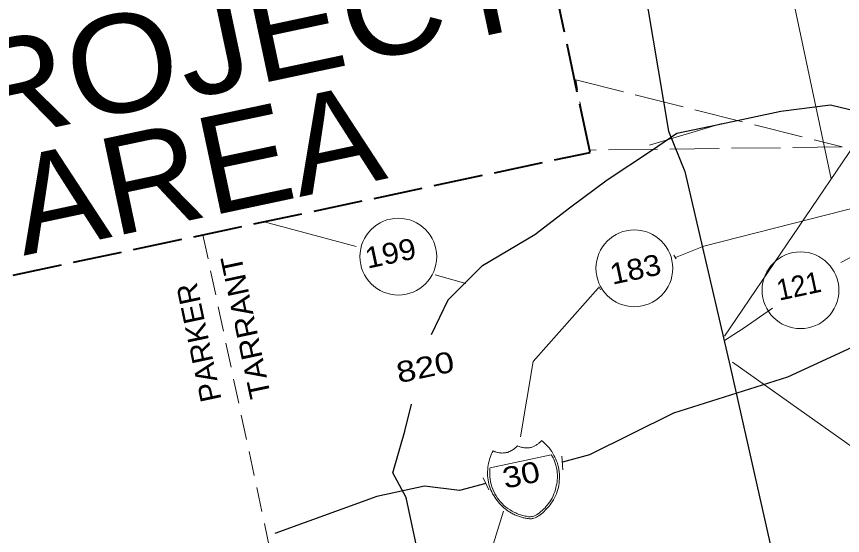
# Model space of a CAD drawing. Extents: x 2357218 to 2371708, y 6973728 to 6980157.
# Drawn here: x 2357321.4 to 2357522.9, y 6974620.2 to 6974746.8 of the extents above; entities that cross this region are included whole.
import ezdxf

# ---------------------------------------------------------------- set-up
doc = ezdxf.new("R2010")
doc.units = 0
doc.header["$LTSCALE"] = 2
doc.linetypes.add('LONG_DASHED', pattern=[7.5, 6, -1.5])
doc.linetypes.add('MEDIUM_DASHED', pattern=[4.5, 3, -1.5])
doc.layers.add('62', color=7, linetype='Continuous', lineweight=13)
doc.layers.add('63', color=7, linetype='Continuous', lineweight=13)

msp = doc.modelspace()

# ---------------------------------------------------------------- linework, layer by layer
at = {"layer": '62'}
for p, q in [((2357520.159, 6974707.242), (2357511.041, 6974750.139)), ((2357529.782, 6974721.388), (2357494.082, 6974668.875)), ((2357475.798, 6974715.388), (2357493.426, 6974720.675)), ((2357381.785, 6974696.74), (2357404.235, 6974690.7)), ((2357522.449, 6974686.841), (2357528.402, 6974689.897)), ((2357481.765, 6974688.614), (2357482.328, 6974687.698)), ((2357423.49, 6974683.774), (2357430.97, 6974681.704)), ((2357463.555, 6974680.671), (2357463.3, 6974680.571)), ((2357463.457, 6974680.927), (2357463.854, 6974680.137)), ((2357498.622, 6974670.689), (2357505.78, 6974675.636)), ((2357498.622, 6974670.689), (2357494.066, 6974667.766)), ((2357454.458, 6974639.583), (2357454.681, 6974636.273)), ((2357435.253, 6974634.282), (2357436.574, 6974631.412)), ((2357440.151, 6974626.169), (2357432.971, 6974602.904))]:
    msp.add_line(p, q, dxfattribs=at)
at = {"layer": '62', "linetype": 'MEDIUM_DASHED'}
msp.add_line((2357366.864, 6974693.567), (2357405.498, 6974511.924), dxfattribs=at)
at = {"layer": '62', "lineweight": 25}
for p, q in [((2357426.636, 6974677.632), (2357422.517, 6974669.187)), ((2357416.135, 6974645.654), (2357417.77, 6974652.238))]:
    msp.add_line(p, q, dxfattribs=at)
at = {"layer": '62', "linetype": 'LONG_DASHED', "lineweight": 40}
msp.add_lwpolyline([(2357277.991, 6974739.919), (2357291.257, 6974677.497), (2357461.31, 6974713.643), (2357448.042, 6974776.064), (2357277.682, 6974739.853)], dxfattribs=at)
at = {"layer": '62', "lineweight": 25}
for points in [[(2357472.928, 6974763.32), (2357480.438, 6974718.79), (2357484.401, 6974709.004)], [(2357426.636, 6974677.632), (2357435.051, 6974686.092), (2357447.82, 6974693.662), (2357456.605, 6974700.382), (2357465.446, 6974706.953), (2357476.319, 6974714.14), (2357482.491, 6974718.329), (2357492.265, 6974720.406), (2357507.868, 6974723.722), (2357519.974, 6974725.216), (2357526.369, 6974723.698), (2357529.782, 6974721.388)], [(2357484.401, 6974709.004), (2357495.501, 6974661.441), (2357507.761, 6974607.022), (2357528.73, 6974538.67), (2357551.355, 6974511.341)], [(2357525.137, 6974666.085), (2357509.492, 6974658.827), (2357481.662, 6974650.034), (2357461.178, 6974639.907), (2357454.572, 6974638.088)], [(2357596.715, 6974637.66), (2357589.374, 6974634.536), (2357579.785, 6974631.6), (2357566.27, 6974627.645), (2357556.498, 6974625.57), (2357549.681, 6974623.223), (2357545.38, 6974619.435), (2357535.992, 6974615.437), (2357522.037, 6974613.553), (2357509.283, 6974611.762), (2357495.348, 6974609.674), (2357474.275, 6974602.318), (2357453.198, 6974600.715), (2357435.858, 6974601.009), (2357424.93, 6974604.275), (2357419.167, 6974616.556), (2357416.416, 6974629.495), (2357413.211, 6974635.486), (2357416.135, 6974645.654)], [(2357435.859, 6974632.939), (2357429.444, 6974631.183), (2357420.936, 6974632.25), (2357409.294, 6974629.777), (2357384.44, 6974620.72)]]:
    msp.add_lwpolyline(points, dxfattribs=at)
at = {"layer": '62', "linetype": 'LONG_DASHED'}
for points in [[(2357457.8, 6974731.348), (2357522.794, 6974714.981), (2357461.163, 6974714.231)], [(2357457.8, 6974731.348), (2357522.794, 6974714.981), (2357461.163, 6974714.231), (2357457.8, 6974731.348)]]:
    msp.add_lwpolyline(points, close=True, dxfattribs=at)
at = {"layer": '62'}
for points in [[(2357556.226, 6974710.287), (2357535.978, 6974702.736), (2357489.081, 6974690.789), (2357482.118, 6974688.043)], [(2357463.3, 6974680.571), (2357447.465, 6974662.645), (2357444.296, 6974644.325)], [(2357544.214, 6974627.95), (2357523.929, 6974642.757), (2357496.053, 6974662.527)], [(2357444.395, 6974641.814), (2357444.611, 6974641.768), (2357444.805, 6974641.719), (2357444.996, 6974641.689), (2357445.212, 6974641.643), (2357445.421, 6974641.641), (2357445.589, 6974641.609), (2357445.794, 6974641.607), (2357445.975, 6974641.621), (2357446.182, 6974641.619), (2357446.369, 6974641.614), (2357446.567, 6974641.655), (2357446.765, 6974641.697), (2357446.941, 6974641.734), (2357447.115, 6974641.772), (2357447.305, 6974641.86), (2357447.472, 6974641.939), (2357447.643, 6974642), (2357447.833, 6974642.086), (2357447.995, 6974642.19), (2357448.162, 6974642.271), (2357448.341, 6974642.4), (2357448.524, 6974642.509), (2357448.682, 6974642.635), (2357448.841, 6974642.761), (2357448.996, 6974642.888), (2357449.149, 6974643.033), (2357449.342, 6974643.213), (2357449.49, 6974643.381), (2357449.796, 6974643.125), (2357450.133, 6974642.849), (2357450.448, 6974642.55), (2357450.749, 6974642.222), (2357451.052, 6974641.873), (2357451.385, 6974641.507), (2357451.675, 6974641.108), (2357451.968, 6974640.711), (2357452.23, 6974640.236), (2357452.485, 6974639.785), (2357452.743, 6974639.335), (2357452.962, 6974638.852), (2357453.156, 6974638.364), (2357453.33, 6974637.872), (2357453.475, 6974637.397), (2357453.609, 6974636.873), (2357453.7, 6974636.339), (2357453.779, 6974635.758), (2357453.829, 6974635.194), (2357453.87, 6974634.675), (2357453.875, 6974634.124), (2357453.809, 6974633.557), (2357453.758, 6974633.039), (2357453.713, 6974632.501), (2357453.597, 6974631.97), (2357453.433, 6974631.43), (2357453.282, 6974630.937), (2357453.099, 6974630.414), (2357452.881, 6974629.91), (2357452.641, 6974629.421), (2357452.378, 6974628.929), (2357452.066, 6974628.446), (2357451.819, 6974628.095), (2357451.576, 6974627.722), (2357451.306, 6974627.365), (2357451.031, 6974627.03), (2357450.709, 6974626.709), (2357450.387, 6974626.389), (2357450.081, 6974626.094), (2357449.776, 6974625.799), (2357449.461, 6974625.549), (2357449.146, 6974625.298), (2357448.827, 6974625.069), (2357448.482, 6974624.856), (2357448.208, 6974624.729), (2357447.898, 6974624.572), (2357447.622, 6974624.467), (2357447.362, 6974624.39)], [(2357447.362, 6974624.39), (2357447.182, 6974624.372), (2357447.029, 6974624.341), (2357446.825, 6974624.32), (2357446.661, 6974624.333), (2357446.497, 6974624.343), (2357446.292, 6974624.346), (2357446.079, 6974624.368), (2357445.865, 6974624.393), (2357445.649, 6974624.439), (2357445.439, 6974624.462), (2357445.193, 6974624.526), (2357444.998, 6974624.576), (2357444.762, 6974624.617), (2357444.539, 6974624.686), (2357444.311, 6974624.776), (2357444.071, 6974624.839), (2357443.842, 6974624.928), (2357443.594, 6974625.014), (2357443.342, 6974625.122), (2357443.138, 6974625.217), (2357442.912, 6974625.307), (2357442.673, 6974625.44), (2357442.422, 6974625.546), (2357442.236, 6974625.669), (2357442.006, 6974625.781), (2357441.797, 6974625.898), (2357441.563, 6974626.03), (2357441.375, 6974626.153), (2357441.161, 6974626.292), (2357440.974, 6974626.413), (2357440.804, 6974626.56), (2357440.614, 6974626.704), (2357440.247, 6974627.016), (2357439.898, 6974627.356), (2357439.55, 6974627.698), (2357439.243, 6974628.045), (2357438.913, 6974628.413), (2357438.605, 6974628.783), (2357438.317, 6974629.16), (2357438.044, 6974629.586), (2357437.803, 6974629.971), (2357437.543, 6974630.424), (2357437.338, 6974630.861), (2357437.128, 6974631.299), (2357436.937, 6974631.767), (2357436.789, 6974632.24), (2357436.634, 6974632.759), (2357436.508, 6974633.236), (2357436.44, 6974633.776), (2357436.38, 6974634.269), (2357436.318, 6974634.784), (2357436.318, 6974635.314), (2357436.323, 6974635.845), (2357436.352, 6974636.356), (2357436.403, 6974636.874), (2357436.448, 6974637.411), (2357436.554, 6974637.895), (2357436.658, 6974638.377), (2357436.789, 6974638.841), (2357436.947, 6974639.288), (2357437.112, 6974639.716), (2357437.258, 6974640.115), (2357437.45, 6974640.501), (2357437.627, 6974640.859), (2357437.853, 6974640.769), (2357438.079, 6974640.679), (2357438.301, 6974640.612), (2357438.473, 6974640.555), (2357438.689, 6974640.509), (2357438.886, 6974640.461), (2357439.099, 6974640.437), (2357439.313, 6974640.392), (2357439.499, 6974640.384), (2357439.69, 6974640.353), (2357439.896, 6974640.353), (2357440.077, 6974640.368), (2357440.286, 6974640.368), (2357440.471, 6974640.36), (2357440.647, 6974640.397), (2357440.868, 6974640.444), (2357441.023, 6974640.477), (2357441.217, 6974640.518), (2357441.387, 6974640.602), (2357441.573, 6974640.686), (2357441.745, 6974640.745), (2357441.912, 6974640.826), (2357442.097, 6974640.937), (2357442.285, 6974641.022), (2357442.421, 6974641.143), (2357442.605, 6974641.249), (2357442.783, 6974641.381), (2357442.962, 6974641.511), (2357443.101, 6974641.63), (2357443.272, 6974641.786), (2357443.42, 6974641.954), (2357443.592, 6974642.127), (2357443.796, 6974642.034), (2357443.979, 6974641.934), (2357444.2, 6974641.866), (2357444.395, 6974641.814)]]:
    msp.add_lwpolyline(points, dxfattribs=at)
msp.add_lwpolyline([(2357451.806, 6974639.941), (2357436.907, 6974636.774), (2357436.888, 6974636.537), (2357436.838, 6974636.231), (2357436.816, 6974635.903), (2357436.836, 6974635.494), (2357436.818, 6974635.03), (2357436.837, 6974634.505), (2357436.905, 6974633.965), (2357437.012, 6974633.346), (2357437.162, 6974632.755), (2357437.342, 6974632.128), (2357437.557, 6974631.551), (2357437.793, 6974630.981), (2357438.073, 6974630.42), (2357438.362, 6974629.93), (2357438.707, 6974629.381), (2357439.063, 6974628.903), (2357439.434, 6974628.454), (2357439.851, 6974628.013), (2357440.289, 6974627.579), (2357440.766, 6974627.172), (2357441.278, 6974626.821), (2357441.792, 6974626.471), (2357442.336, 6974626.174), (2357442.905, 6974625.879), (2357443.166, 6974625.729), (2357443.463, 6974625.63), (2357443.748, 6974625.482), (2357444.066, 6974625.389), (2357444.32, 6974625.284), (2357444.617, 6974625.184), (2357444.909, 6974625.109), (2357445.222, 6974625.039), (2357445.489, 6974624.979), (2357445.776, 6974624.926), (2357446.064, 6974624.872), (2357446.303, 6974624.831), (2357446.56, 6974624.816), (2357446.786, 6974624.819), (2357447.034, 6974624.849), (2357447.26, 6974624.873), (2357447.555, 6974624.983), (2357447.922, 6974625.105), (2357448.224, 6974625.309), (2357448.615, 6974625.528), (2357448.956, 6974625.763), (2357449.284, 6974626.063), (2357449.637, 6974626.346), (2357449.981, 6974626.671), (2357450.324, 6974627.02), (2357450.612, 6974627.379), (2357450.91, 6974627.718), (2357451.201, 6974628.081), (2357451.475, 6974628.415), (2357451.684, 6974628.733), (2357451.887, 6974629.076), (2357452.033, 6974629.361), (2357452.265, 6974629.892), (2357452.479, 6974630.399), (2357452.673, 6974630.9), (2357452.837, 6974631.418), (2357452.969, 6974631.883), (2357453.075, 6974632.365), (2357453.181, 6974632.826), (2357453.243, 6974633.297), (2357453.304, 6974633.77), (2357453.35, 6974634.196), (2357453.345, 6974634.655), (2357453.324, 6974635.087), (2357453.278, 6974635.515), (2357453.256, 6974635.948), (2357453.165, 6974636.365), (2357453.105, 6974636.764), (2357452.952, 6974637.376), (2357452.795, 6974637.894), (2357452.621, 6974638.389), (2357452.461, 6974638.813), (2357452.267, 6974639.187), (2357452.092, 6974639.471), (2357451.945, 6974639.74)], close=True, dxfattribs=at)
for centre in [(2357414.526, 6974688.233), (2357472.114, 6974685.387), (2357512.647, 6974680.037)]:
    msp.add_circle(centre, 9.364, dxfattribs=at)
at = {"layer": '63'}
for p, q in [((2357520.159, 6974707.242), (2357511.041, 6974750.139)), ((2357529.782, 6974721.388), (2357494.082, 6974668.875)), ((2357475.798, 6974715.388), (2357493.426, 6974720.675)), ((2357381.785, 6974696.74), (2357404.235, 6974690.7)), ((2357522.449, 6974686.841), (2357528.402, 6974689.897)), ((2357481.765, 6974688.614), (2357482.328, 6974687.698)), ((2357423.49, 6974683.774), (2357430.97, 6974681.704)), ((2357463.555, 6974680.671), (2357463.3, 6974680.571)), ((2357463.457, 6974680.927), (2357463.854, 6974680.137)), ((2357498.622, 6974670.689), (2357505.78, 6974675.636)), ((2357498.622, 6974670.689), (2357494.066, 6974667.766)), ((2357454.458, 6974639.583), (2357454.681, 6974636.273)), ((2357435.253, 6974634.282), (2357436.574, 6974631.412)), ((2357440.151, 6974626.169), (2357432.971, 6974602.904))]:
    msp.add_line(p, q, dxfattribs=at)
at = {"layer": '63', "linetype": 'MEDIUM_DASHED'}
msp.add_line((2357366.864, 6974693.567), (2357405.498, 6974511.924), dxfattribs=at)
at = {"layer": '63', "lineweight": 25}
for p, q in [((2357426.636, 6974677.632), (2357422.517, 6974669.187)), ((2357416.135, 6974645.654), (2357417.77, 6974652.238))]:
    msp.add_line(p, q, dxfattribs=at)
at = {"layer": '63', "linetype": 'LONG_DASHED', "lineweight": 40}
msp.add_lwpolyline([(2357277.991, 6974739.919), (2357291.257, 6974677.497), (2357461.31, 6974713.643), (2357448.042, 6974776.064), (2357277.682, 6974739.853)], dxfattribs=at)
at = {"layer": '63', "lineweight": 25}
for points in [[(2357472.928, 6974763.32), (2357480.438, 6974718.79), (2357484.401, 6974709.004)], [(2357426.636, 6974677.632), (2357435.051, 6974686.092), (2357447.82, 6974693.662), (2357456.605, 6974700.382), (2357465.446, 6974706.953), (2357476.319, 6974714.14), (2357482.491, 6974718.329), (2357492.265, 6974720.406), (2357507.868, 6974723.722), (2357519.974, 6974725.216), (2357526.369, 6974723.698), (2357529.782, 6974721.388)], [(2357484.401, 6974709.004), (2357495.501, 6974661.441), (2357507.761, 6974607.022), (2357528.73, 6974538.67), (2357551.355, 6974511.341)], [(2357525.137, 6974666.085), (2357509.492, 6974658.827), (2357481.662, 6974650.034), (2357461.178, 6974639.907), (2357454.572, 6974638.088)], [(2357596.715, 6974637.66), (2357589.374, 6974634.536), (2357579.785, 6974631.6), (2357566.27, 6974627.645), (2357556.498, 6974625.57), (2357549.681, 6974623.223), (2357545.38, 6974619.435), (2357535.992, 6974615.437), (2357522.037, 6974613.553), (2357509.283, 6974611.762), (2357495.348, 6974609.674), (2357474.275, 6974602.318), (2357453.198, 6974600.715), (2357435.858, 6974601.009), (2357424.93, 6974604.275), (2357419.167, 6974616.556), (2357416.416, 6974629.495), (2357413.211, 6974635.486), (2357416.135, 6974645.654)], [(2357435.859, 6974632.939), (2357429.444, 6974631.183), (2357420.936, 6974632.25), (2357409.294, 6974629.777), (2357384.44, 6974620.72)]]:
    msp.add_lwpolyline(points, dxfattribs=at)
at = {"layer": '63', "linetype": 'LONG_DASHED'}
for points in [[(2357457.8, 6974731.348), (2357522.794, 6974714.981), (2357461.163, 6974714.231)], [(2357457.8, 6974731.348), (2357522.794, 6974714.981), (2357461.163, 6974714.231), (2357457.8, 6974731.348)]]:
    msp.add_lwpolyline(points, close=True, dxfattribs=at)
at = {"layer": '63'}
for points in [[(2357556.226, 6974710.287), (2357535.978, 6974702.736), (2357489.081, 6974690.789), (2357482.118, 6974688.043)], [(2357463.3, 6974680.571), (2357447.465, 6974662.645), (2357444.296, 6974644.325)], [(2357544.214, 6974627.95), (2357523.929, 6974642.757), (2357496.053, 6974662.527)], [(2357444.395, 6974641.814), (2357444.611, 6974641.768), (2357444.805, 6974641.719), (2357444.996, 6974641.689), (2357445.212, 6974641.643), (2357445.421, 6974641.641), (2357445.589, 6974641.609), (2357445.794, 6974641.607), (2357445.975, 6974641.621), (2357446.182, 6974641.619), (2357446.369, 6974641.614), (2357446.567, 6974641.655), (2357446.765, 6974641.697), (2357446.941, 6974641.734), (2357447.115, 6974641.772), (2357447.305, 6974641.86), (2357447.472, 6974641.939), (2357447.643, 6974642), (2357447.833, 6974642.086), (2357447.995, 6974642.19), (2357448.162, 6974642.271), (2357448.341, 6974642.4), (2357448.524, 6974642.509), (2357448.682, 6974642.635), (2357448.841, 6974642.761), (2357448.996, 6974642.888), (2357449.149, 6974643.033), (2357449.342, 6974643.213), (2357449.49, 6974643.381), (2357449.796, 6974643.125), (2357450.133, 6974642.849), (2357450.448, 6974642.55), (2357450.749, 6974642.222), (2357451.052, 6974641.873), (2357451.385, 6974641.507), (2357451.675, 6974641.108), (2357451.968, 6974640.711), (2357452.23, 6974640.236), (2357452.485, 6974639.785), (2357452.743, 6974639.335), (2357452.962, 6974638.852), (2357453.156, 6974638.364), (2357453.33, 6974637.872), (2357453.475, 6974637.397), (2357453.609, 6974636.873), (2357453.7, 6974636.339), (2357453.779, 6974635.758), (2357453.829, 6974635.194), (2357453.87, 6974634.675), (2357453.875, 6974634.124), (2357453.809, 6974633.557), (2357453.758, 6974633.039), (2357453.713, 6974632.501), (2357453.597, 6974631.97), (2357453.433, 6974631.43), (2357453.282, 6974630.937), (2357453.099, 6974630.414), (2357452.881, 6974629.91), (2357452.641, 6974629.421), (2357452.378, 6974628.929), (2357452.066, 6974628.446), (2357451.819, 6974628.095), (2357451.576, 6974627.722), (2357451.306, 6974627.365), (2357451.031, 6974627.03), (2357450.709, 6974626.709), (2357450.387, 6974626.389), (2357450.081, 6974626.094), (2357449.776, 6974625.799), (2357449.461, 6974625.549), (2357449.146, 6974625.298), (2357448.827, 6974625.069), (2357448.482, 6974624.856), (2357448.208, 6974624.729), (2357447.898, 6974624.572), (2357447.622, 6974624.467), (2357447.362, 6974624.39)], [(2357447.362, 6974624.39), (2357447.182, 6974624.372), (2357447.029, 6974624.341), (2357446.825, 6974624.32), (2357446.661, 6974624.333), (2357446.497, 6974624.343), (2357446.292, 6974624.346), (2357446.079, 6974624.368), (2357445.865, 6974624.393), (2357445.649, 6974624.439), (2357445.439, 6974624.462), (2357445.193, 6974624.526), (2357444.998, 6974624.576), (2357444.762, 6974624.617), (2357444.539, 6974624.686), (2357444.311, 6974624.776), (2357444.071, 6974624.839), (2357443.842, 6974624.928), (2357443.594, 6974625.014), (2357443.342, 6974625.122), (2357443.138, 6974625.217), (2357442.912, 6974625.307), (2357442.673, 6974625.44), (2357442.422, 6974625.546), (2357442.236, 6974625.669), (2357442.006, 6974625.781), (2357441.797, 6974625.898), (2357441.563, 6974626.03), (2357441.375, 6974626.153), (2357441.161, 6974626.292), (2357440.974, 6974626.413), (2357440.804, 6974626.56), (2357440.614, 6974626.704), (2357440.247, 6974627.016), (2357439.898, 6974627.356), (2357439.55, 6974627.698), (2357439.243, 6974628.045), (2357438.913, 6974628.413), (2357438.605, 6974628.783), (2357438.317, 6974629.16), (2357438.044, 6974629.586), (2357437.803, 6974629.971), (2357437.543, 6974630.424), (2357437.338, 6974630.861), (2357437.128, 6974631.299), (2357436.937, 6974631.767), (2357436.789, 6974632.24), (2357436.634, 6974632.759), (2357436.508, 6974633.236), (2357436.44, 6974633.776), (2357436.38, 6974634.269), (2357436.318, 6974634.784), (2357436.318, 6974635.314), (2357436.323, 6974635.845), (2357436.352, 6974636.356), (2357436.403, 6974636.874), (2357436.448, 6974637.411), (2357436.554, 6974637.895), (2357436.658, 6974638.377), (2357436.789, 6974638.841), (2357436.947, 6974639.288), (2357437.112, 6974639.716), (2357437.258, 6974640.115), (2357437.45, 6974640.501), (2357437.627, 6974640.859), (2357437.853, 6974640.769), (2357438.079, 6974640.679), (2357438.301, 6974640.612), (2357438.473, 6974640.555), (2357438.689, 6974640.509), (2357438.886, 6974640.461), (2357439.099, 6974640.437), (2357439.313, 6974640.392), (2357439.499, 6974640.384), (2357439.69, 6974640.353), (2357439.896, 6974640.353), (2357440.077, 6974640.368), (2357440.286, 6974640.368), (2357440.471, 6974640.36), (2357440.647, 6974640.397), (2357440.868, 6974640.444), (2357441.023, 6974640.477), (2357441.217, 6974640.518), (2357441.387, 6974640.602), (2357441.573, 6974640.686), (2357441.745, 6974640.745), (2357441.912, 6974640.826), (2357442.097, 6974640.937), (2357442.285, 6974641.022), (2357442.421, 6974641.143), (2357442.605, 6974641.249), (2357442.783, 6974641.381), (2357442.962, 6974641.511), (2357443.101, 6974641.63), (2357443.272, 6974641.786), (2357443.42, 6974641.954), (2357443.592, 6974642.127), (2357443.796, 6974642.034), (2357443.979, 6974641.934), (2357444.2, 6974641.866), (2357444.395, 6974641.814)]]:
    msp.add_lwpolyline(points, dxfattribs=at)
msp.add_lwpolyline([(2357451.806, 6974639.941), (2357436.907, 6974636.774), (2357436.888, 6974636.537), (2357436.838, 6974636.231), (2357436.816, 6974635.903), (2357436.836, 6974635.494), (2357436.818, 6974635.03), (2357436.837, 6974634.505), (2357436.905, 6974633.965), (2357437.012, 6974633.346), (2357437.162, 6974632.755), (2357437.342, 6974632.128), (2357437.557, 6974631.551), (2357437.793, 6974630.981), (2357438.073, 6974630.42), (2357438.362, 6974629.93), (2357438.707, 6974629.381), (2357439.063, 6974628.903), (2357439.434, 6974628.454), (2357439.851, 6974628.013), (2357440.289, 6974627.579), (2357440.766, 6974627.172), (2357441.278, 6974626.821), (2357441.792, 6974626.471), (2357442.336, 6974626.174), (2357442.905, 6974625.879), (2357443.166, 6974625.729), (2357443.463, 6974625.63), (2357443.748, 6974625.482), (2357444.066, 6974625.389), (2357444.32, 6974625.284), (2357444.617, 6974625.184), (2357444.909, 6974625.109), (2357445.222, 6974625.039), (2357445.489, 6974624.979), (2357445.776, 6974624.926), (2357446.064, 6974624.872), (2357446.303, 6974624.831), (2357446.56, 6974624.816), (2357446.786, 6974624.819), (2357447.034, 6974624.849), (2357447.26, 6974624.873), (2357447.555, 6974624.983), (2357447.922, 6974625.105), (2357448.224, 6974625.309), (2357448.615, 6974625.528), (2357448.956, 6974625.763), (2357449.284, 6974626.063), (2357449.637, 6974626.346), (2357449.981, 6974626.671), (2357450.324, 6974627.02), (2357450.612, 6974627.379), (2357450.91, 6974627.718), (2357451.201, 6974628.081), (2357451.475, 6974628.415), (2357451.684, 6974628.733), (2357451.887, 6974629.076), (2357452.033, 6974629.361), (2357452.265, 6974629.892), (2357452.479, 6974630.399), (2357452.673, 6974630.9), (2357452.837, 6974631.418), (2357452.969, 6974631.883), (2357453.075, 6974632.365), (2357453.181, 6974632.826), (2357453.243, 6974633.297), (2357453.304, 6974633.77), (2357453.35, 6974634.196), (2357453.345, 6974634.655), (2357453.324, 6974635.087), (2357453.278, 6974635.515), (2357453.256, 6974635.948), (2357453.165, 6974636.365), (2357453.105, 6974636.764), (2357452.952, 6974637.376), (2357452.795, 6974637.894), (2357452.621, 6974638.389), (2357452.461, 6974638.813), (2357452.267, 6974639.187), (2357452.092, 6974639.471), (2357451.945, 6974639.74)], close=True, dxfattribs=at)
for centre in [(2357414.526, 6974688.233), (2357472.114, 6974685.387), (2357512.647, 6974680.037)]:
    msp.add_circle(centre, 9.364, dxfattribs=at)

# ---------------------------------------------------------------- texts
at = {"layer": '62'}
for s, height, rotation, width, p in [('PROJECT', 23.83, 12, 1.1, (2357288.665, 6974710.81)), ('AREA', 23.83, 12, 1.05, (2357323.092, 6974688.451)), ('199', 5.099, 12, 1.1, (2357407.017, 6974685.289)), ('183', 5.099, 12, 1.1, (2357466.766, 6974681.378)), ('TARRANT', 5.099, 102, 1.1, (2357383.453, 6974654.261)), ('121', 5.099, 12, 0.95, (2357507.459, 6974677.491)), ('PARKER', 5.099, 102, 1.05, (2357371.42, 6974653.406)), ('820', 5.099, 12, 1.25, (2357414.659, 6974657.352)), ('30', 5.099, 12, 1.2, (2357440.581, 6974631.621))]:
    msp.add_text(s, height=height, rotation=rotation, dxfattribs=dict(at, width=width)).set_placement(p)
at = {"layer": '63'}
for s, height, rotation, width, p in [('PROJECT', 23.83, 12, 1.1, (2357288.665, 6974710.81)), ('AREA', 23.83, 12, 1.05, (2357323.092, 6974688.451)), ('199', 5.099, 12, 1.1, (2357407.017, 6974685.289)), ('183', 5.099, 12, 1.1, (2357466.766, 6974681.378)), ('TARRANT', 5.099, 102, 1.1, (2357383.453, 6974654.261)), ('121', 5.099, 12, 0.95, (2357507.459, 6974677.491)), ('PARKER', 5.099, 102, 1.05, (2357371.42, 6974653.406)), ('820', 5.099, 12, 1.25, (2357414.659, 6974657.352)), ('30', 5.099, 12, 1.2, (2357440.581, 6974631.621))]:
    msp.add_text(s, height=height, rotation=rotation, dxfattribs=dict(at, width=width)).set_placement(p)

doc.saveas('drawing.dxf')
